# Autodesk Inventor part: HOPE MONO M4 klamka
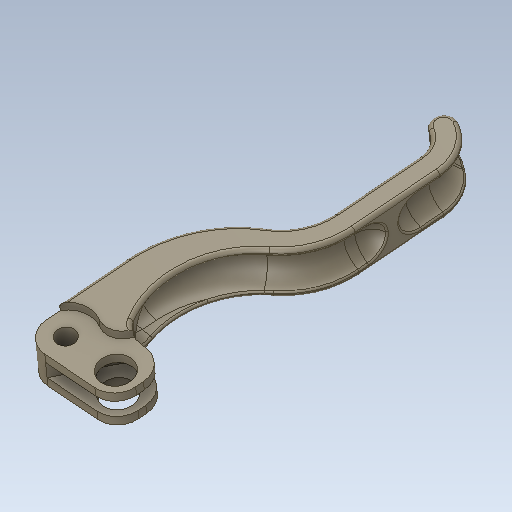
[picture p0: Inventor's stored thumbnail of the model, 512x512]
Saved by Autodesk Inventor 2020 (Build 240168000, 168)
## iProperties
Created: 2015-11
Part Number: HOPE MONO M4 klamka
Material: Ogólny
Document SubType Name: Modeling
Designer: Tomasz
Density: 1 g/cm^3
Appearance: Domyślna
Sending System: SolidWorks 2017
Last Author: Tomasz
Last Saved: 2017-11-19
Author: Tomasz
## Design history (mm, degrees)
feature "Imported1"
node "Bryła1"
